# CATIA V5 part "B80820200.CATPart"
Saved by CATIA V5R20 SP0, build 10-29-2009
Part number: B80820200
Revision: 6
Definition: design
Nomenclature: B80820200
Source: made
Description: NOT SPECIFIED
Bounding box of the stored display mesh (mm): x -11.818 to 11.818, y -12 to 12, z 0 to 200
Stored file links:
  C:\Users\Raffaele\Desktop\3D X SITO CF\BOLEX\4-PILLAR REF 808\B80820200.CATPart
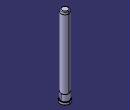
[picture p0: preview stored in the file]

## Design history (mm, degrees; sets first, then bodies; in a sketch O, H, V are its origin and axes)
Body1 "MANIFOLD_SOLID_BREP #450" (main body)
  Solid1: solid without history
